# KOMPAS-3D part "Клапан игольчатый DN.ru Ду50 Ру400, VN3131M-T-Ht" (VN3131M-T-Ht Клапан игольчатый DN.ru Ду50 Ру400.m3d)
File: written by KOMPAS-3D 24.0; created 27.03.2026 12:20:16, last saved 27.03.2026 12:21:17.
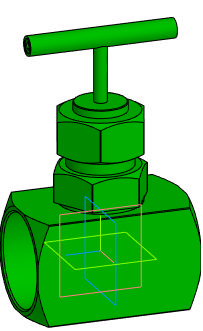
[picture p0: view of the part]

Document properties: Автор: Илья; Полное имя файла: D:\Обмен\Заказы с фриланса\DN.ru\VNxxM-T-Ht Клапан игольчатый DN.ru Ду8-50 Ру400\VN3131M-T-Ht Клапан игольчатый DN.ru Ду8-50 Ру400\DN50\VN3131M-T-Ht Клапан игольчатый DN.ru Ду50 Ру400.m3d

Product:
- Body: Body1  | qty 1
    Масса: 2.961611
- Part/product: Клапан игольчатый DN.ru Ду50 Ру400  | designation VN3131M-T-Ht
    Масса: 3
    Раздел спецификации: Прочие изделия
    Примечание: D090-02136

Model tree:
1. Body1  (labels: Body1)

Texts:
  VN3131M-T-Ht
